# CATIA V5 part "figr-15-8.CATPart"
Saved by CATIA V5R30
Part number: Part1
Bounding box of the stored display mesh (mm): x -50 to 50, y -32.5 to 33.5, z -52 to 1
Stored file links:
  D:\PROJECTS\CATIA V56R 2020\Resources\Parts File\c15_catia_v5_6r2020_prt\figr-15-8.CATPart
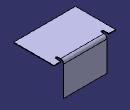
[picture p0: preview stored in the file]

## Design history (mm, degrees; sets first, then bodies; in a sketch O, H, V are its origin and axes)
SheetMetalParameters1: Thickness 1, BendRadius 4, KFactor 0.475772 {= log(min(100,max(20*SheetMetalParameters1.BendRadius,SheetMetalParameters1.Thickness)/SheetMetalParameters1.Thickness))/log(100)/2}, ReliefRadialLength 4, ReliefAxialLength 4, MinimumBendRadius 0
Body1 (main body)
  Sketch1 on xy-plane, origin (0, 0, 0), H (1, 0, 0), V (0, 1, 0)
    line L1 (-50, 32.5) -> (50, 32.5)
    line L2 (50, 32.5) -> (50, -32.5)
    line L3 (50, -32.5) -> (-50, -32.5)
    line L4 (-50, -32.5) -> (-50, 32.5)
    length L1 = 100
    length L2 = 65
    horizontal: L1 H, L3 H
    vertical: L2 V, L4 V
    symmetry: L4 L2 V, L1 L3 H
  Wall1: Thickness 1, Profile Sketch1
  d_NewWallOnEdge1: NewWallOnEdge_Edge edge [face of Wall1 | face of Wall1], NewWallOnEdge_Length 53, NewWallOnEdge_HeightLimitOffset 0, NewWallOnEdge_WidthOffset1 -15, NewWallOnEdge_WidthOffset2 -15, NewWallOnEdge_Angle 90, NewWallOnEdge_BendRadiusValue 4 {= SheetMetalParameters1.BendRadius}, NewWallOnEdge_BendTable SheetMetalParameters1, KFacteur 0.475772 {= log(min(100,max(20*d_NewWallOnEdge1.Radius,SheetMetalParameters1.Thickness)/SheetMetalParameters1.Thickness))/log(100)/2}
